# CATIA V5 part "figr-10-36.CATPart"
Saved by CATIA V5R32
Part number: Part1
Bounding box of the stored display mesh (mm): x -85.282 to 128.744, y -7.97 to 191.596, z 0 to 148.964
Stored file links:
  D:\PROJECTS\Project 2022\CATIA V5 6R 2022\Resources\Part Files\c10_catia_v5_6r2022_prt\c10_catia_v5_6r2022_prt\figr-10-36.CATPart
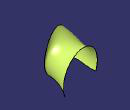
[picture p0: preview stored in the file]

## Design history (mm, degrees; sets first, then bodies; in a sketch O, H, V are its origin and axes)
Set1
  Sketch1 on xy-plane, origin (0, 0, 0), H (1, 0, 0), V (0, 1, 0)
    spline S1 through (-60, 0) (-70, 70) (-70, 170) (-80, 190)
  Sketch2 on yz-plane, origin (0, 0, 0), H (0, 1, 0), V (0, 0, 1)
    spline S1 through (0, 170) (100, 120) (180, 150)
  Sketch3 on xy-plane, origin (0, 0, 0), H (1, 0, 0), V (0, 1, 0)
    spline S1 through (70, 0) (70, 80) (120, 190)
  Sweep1: type Circle, Guide (Sketch1; Sketch2; Sketch3)
Body1 (main body)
